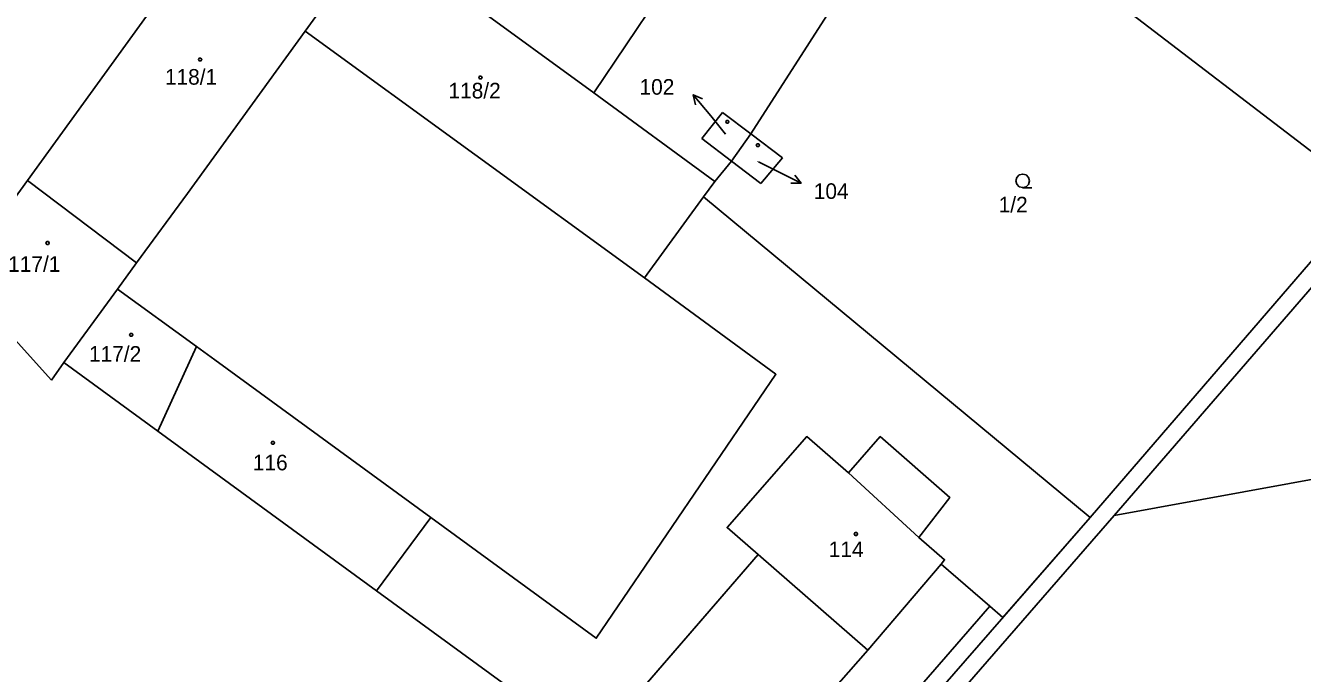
# Model space of a CAD drawing. Extents: x -850689 to -847910, y -1058374 to -1054747.
# Drawn here: x -849326.1 to -849187.1, y -1056444.2 to -1056373.6 of the extents above; entities that cross this region are included whole.
import ezdxf

# ---------------------------------------------------------------- set-up
doc = ezdxf.new("R2010")
doc.units = 0
for name, color, linetype in [('KN_BREMENA', 7, 'Continuous'), ('KN_HRANICE', 7, 'Continuous'), ('KN_KULTURY', 7, 'Continuous'), ('KN_PARCELY', 7, 'Continuous'), ('KN_SLUCKY', 7, 'Continuous'), ('KN_STAVEBNI', 7, 'Continuous')]:
    doc.layers.add(name, color=color, linetype=linetype)

# ---------------------------------------------------------------- blocks, each defined once
blk = doc.blocks.new('304')
blk.add_lwpolyline([(0, 0), (-0.38, 0.1), (-0.65, 0.37), (-0.75, 0.74), (-0.65, 1.11), (-0.38, 1.38), (-0.01, 1.48), (0.36, 1.38), (0.63, 1.11), (0.73, 0.73), (0.63, 0.35), (0.36, 0.08), (-0.02, -0.02), (0.98, -0.02)])
blk = doc.blocks.new('NAHRADNI_SYMBOL')
blk.add_lwpolyline([(0.09, 0.15), (0.18, 0), (0.09, -0.15), (-0.09, -0.15), (-0.18, 0), (-0.09, 0.15), (0.09, 0.15)])
blk = doc.blocks.new('10292')
blk.add_line((0, 3), (0, 0))
blk.add_lwpolyline([(-0.5, 2), (0, 3), (0.5, 2)])
blk = doc.blocks.new('402')
blk.add_lwpolyline([(0.09, 0.15), (0.18, 0), (0.09, -0.15), (-0.09, -0.15), (-0.18, 0), (-0.09, 0.15), (0.09, 0.15)])

msp = doc.modelspace()

# ---------------------------------------------------------------- linework, layer by layer
at = {"layer": 'KN_BREMENA'}
for points in [[(-849355.23, -1056367.43), (-849351.69, -1056370.82), (-849349.93, -1056375.07), (-849350.77, -1056418.49), (-849350.24, -1056427.3), (-849345.77, -1056436.61), (-849342.23, -1056439.43), (-849327.01, -1056449.14), (-849298.02, -1056468.19), (-849284.6, -1056463.96), (-849270.77, -1056447.7), (-849287.91, -1056435.18), (-849282.02, -1056427.2), (-849264.01, -1056440.34), (-849244.44, -1056411.59), (-849258.75, -1056401.09), (-849252.32, -1056392.28), (-849210.21, -1056427.21)], [(-849228.87, -1056429.39), (-849225.51, -1056425.01), (-849233.09, -1056418.39), (-849236.55, -1056422.35), (-849241.09, -1056418.38), (-849249.75, -1056428.29), (-849246.39, -1056431.22), (-849295.7, -1056488.26), (-849284.26, -1056498.23), (-849262.65, -1056473.57), (-849257.24, -1056478.3), (-849255.9, -1056479.47)], [(-849210.21, -1056427.21), (-849219.72, -1056438.09), (-849221.16, -1056436.85), (-849226.46, -1056432.26)], [(-849226.46, -1056432.26), (-849226.07, -1056431.8), (-849228.87, -1056429.39)]]:
    msp.add_lwpolyline(points, dxfattribs=at)
at = {"layer": 'KN_HRANICE'}
for p, q in [((-849264.25, -1056380.97), (-849243.84, -1056350.56)), ((-849299.09, -1056353.44), (-849325.93, -1056390.5)), ((-849288.04, -1056363.64), (-849295.68, -1056374.24)), ((-849215.1, -1056365.17), (-849179.95, -1056392.09)), ((-849235.05, -1056366.54), (-849247.17, -1056385.43)), ((-849264.25, -1056380.97), (-849277.71, -1056371.17)), ((-849295.68, -1056374.24), (-849308.52, -1056391.92)), ((-849258.75, -1056401.09), (-849295.68, -1056374.24)), ((-849251.09, -1056390.6), (-849264.25, -1056380.97)), ((-849207.62, -1056426.96), (-849167.05, -1056380.13)), ((-849252.49, -1056385.93), (-849250.27, -1056383.09)), ((-849250.27, -1056383.09), (-849247.17, -1056385.43)), ((-849249.26, -1056388.39), (-849252.49, -1056385.93)), ((-849249.26, -1056388.39), (-849247.17, -1056385.43)), ((-849247.17, -1056385.43), (-849243.74, -1056388.04)), ((-849251.09, -1056390.6), (-849249.26, -1056388.39)), ((-849246.07, -1056390.82), (-849249.26, -1056388.39)), ((-849243.74, -1056388.04), (-849246.07, -1056390.82)), ((-849325.93, -1056390.5), (-849333.53, -1056401)), ((-849314.04, -1056399.47), (-849325.93, -1056390.5)), ((-849252.32, -1056392.28), (-849251.09, -1056390.6)), ((-849308.52, -1056391.92), (-849314.04, -1056399.47)), ((-849210.21, -1056427.21), (-849179.95, -1056392.09)), ((-849258.75, -1056401.09), (-849252.32, -1056392.28)), ((-849252.32, -1056392.28), (-849210.21, -1056427.21)), ((-849314.04, -1056399.47), (-849316.13, -1056402.34)), ((-849333.53, -1056401), (-849323.3, -1056412.23)), ((-849316.13, -1056402.34), (-849321.97, -1056410.33)), ((-849316.13, -1056402.34), (-849307.54, -1056408.56)), ((-849311.74, -1056417.78), (-849307.54, -1056408.56)), ((-849307.54, -1056408.56), (-849305.54, -1056410.02)), ((-849305.54, -1056410.02), (-849282.02, -1056427.2)), ((-849321.97, -1056410.33), (-849323.3, -1056412.23)), ((-849311.74, -1056417.78), (-849321.97, -1056410.33)), ((-849287.91, -1056435.18), (-849311.74, -1056417.78)), ((-849249.75, -1056428.29), (-849241.09, -1056418.38)), ((-849241.09, -1056418.38), (-849236.55, -1056422.35)), ((-849236.55, -1056422.35), (-849233.09, -1056418.39)), ((-849225.51, -1056425.01), (-849233.09, -1056418.39)), ((-849174.42, -1056420.91), (-849207.62, -1056426.96)), ((-849225.51, -1056425.01), (-849228.87, -1056429.39)), ((-849210.21, -1056427.21), (-849289.39, -1056517.79)), ((-849289.35, -1056520.97), (-849207.62, -1056426.96)), ((-849282.02, -1056427.2), (-849287.91, -1056435.18)), ((-849246.39, -1056431.22), (-849249.75, -1056428.29)), ((-849228.87, -1056429.39), (-849226.07, -1056431.8)), ((-849295.7, -1056488.26), (-849246.39, -1056431.22)), ((-849234.42, -1056441.65), (-849246.39, -1056431.22)), ((-849234.42, -1056441.65), (-849226.46, -1056432.26)), ((-849226.46, -1056432.26), (-849226.07, -1056431.8)), ((-849221.16, -1056436.85), (-849226.46, -1056432.26)), ((-849257.24, -1056478.3), (-849221.16, -1056436.85))]:
    msp.add_line(p, q, dxfattribs=at)
at = {"layer": 'KN_PARCELY'}
for p, q in [((-849249.93, -1056385.45), (-849251.54, -1056383.48)), ((-849246.35, -1056388.48), (-849244.39, -1056389.46))]:
    msp.add_line(p, q, dxfattribs=at)
at = {"layer": 'KN_SLUCKY'}
for p, q in [((-849228.87, -1056429.39), (-849236.55, -1056422.35)), ((-849262.65, -1056473.57), (-849234.42, -1056441.65))]:
    msp.add_line(p, q, dxfattribs=at)
at = {"layer": 'KN_STAVEBNI'}
for p, q in [((-849299.09, -1056353.44), (-849325.93, -1056390.5)), ((-849288.04, -1056363.64), (-849295.68, -1056374.24)), ((-849295.68, -1056374.24), (-849308.52, -1056391.92)), ((-849252.49, -1056385.93), (-849250.27, -1056383.09)), ((-849250.27, -1056383.09), (-849247.17, -1056385.43)), ((-849249.26, -1056388.39), (-849252.49, -1056385.93)), ((-849249.26, -1056388.39), (-849247.17, -1056385.43)), ((-849249.26, -1056388.39), (-849247.17, -1056385.43)), ((-849247.17, -1056385.43), (-849243.74, -1056388.04)), ((-849246.07, -1056390.82), (-849249.26, -1056388.39)), ((-849243.74, -1056388.04), (-849246.07, -1056390.82)), ((-849325.93, -1056390.5), (-849333.53, -1056401)), ((-849314.04, -1056399.47), (-849325.93, -1056390.5)), ((-849314.04, -1056399.47), (-849325.93, -1056390.5)), ((-849308.52, -1056391.92), (-849314.04, -1056399.47)), ((-849314.04, -1056399.47), (-849316.13, -1056402.34)), ((-849333.53, -1056401), (-849323.3, -1056412.23)), ((-849316.13, -1056402.34), (-849321.97, -1056410.33)), ((-849311.74, -1056417.78), (-849307.54, -1056408.56)), ((-849307.54, -1056408.56), (-849305.54, -1056410.02)), ((-849305.54, -1056410.02), (-849282.02, -1056427.2)), ((-849321.97, -1056410.33), (-849323.3, -1056412.23)), ((-849287.91, -1056435.18), (-849311.74, -1056417.78)), ((-849249.75, -1056428.29), (-849241.09, -1056418.38)), ((-849241.09, -1056418.38), (-849236.55, -1056422.35)), ((-849228.87, -1056429.39), (-849236.55, -1056422.35)), ((-849282.02, -1056427.2), (-849287.91, -1056435.18)), ((-849246.39, -1056431.22), (-849249.75, -1056428.29)), ((-849228.87, -1056429.39), (-849226.07, -1056431.8)), ((-849295.7, -1056488.26), (-849246.39, -1056431.22)), ((-849234.42, -1056441.65), (-849246.39, -1056431.22)), ((-849234.42, -1056441.65), (-849246.39, -1056431.22)), ((-849234.42, -1056441.65), (-849226.46, -1056432.26)), ((-849226.46, -1056432.26), (-849226.07, -1056431.8)), ((-849262.65, -1056473.57), (-849234.42, -1056441.65))]:
    msp.add_line(p, q, dxfattribs=at)

# ---------------------------------------------------------------- block references
at = {"layer": 'KN_KULTURY'}
for name, p in [('402', (-849307.13, -1056377.33)), ('NAHRADNI_SYMBOL', (-849276.61, -1056379.29)), ('402', (-849249.73, -1056384.11)), ('402', (-849246.4, -1056386.67)), ('304', (-849217.56, -1056391.28)), ('402', (-849323.74, -1056397.31)), ('NAHRADNI_SYMBOL', (-849314.63, -1056407.31)), ('402', (-849299.2, -1056419.06)), ('402', (-849235.73, -1056428.99))]:
    msp.add_blockref(name, p, dxfattribs=at)
at = {"layer": 'KN_PARCELY'}
for p, rotation in [((-849251.54, -1056383.48), 39.304905), ((-849244.39, -1056389.46), -116.66482400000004)]:
    msp.add_blockref('10292', p, dxfattribs=dict(at, rotation=rotation))

# ---------------------------------------------------------------- texts
for s, height, p in [('118/1', 1.7, (-849310.96, -1056380.07)), ('102', 1.7, (-849259.29, -1056381.16)), ('118/2', 1.7, (-849280.09, -1056381.57)), ('102', 0.1, (-849250.08, -1056385.45)), ('104', 0.1, (-849246.5, -1056388.48)), ('104', 1.7, (-849240.32, -1056392.51)), ('1/2', 1.7, (-849220.19, -1056393.98)), ('117/1', 1.7, (-849328.03, -1056400.45)), ('117/2', 1.7, (-849319.23, -1056410.23)), ('116', 1.7, (-849301.39, -1056422.06)), ('114', 1.7, (-849238.69, -1056431.51))]:
    msp.add_text(s, height=height, dxfattribs=at).set_placement(p)

doc.saveas('drawing.dxf')
